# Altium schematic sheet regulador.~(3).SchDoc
size A4
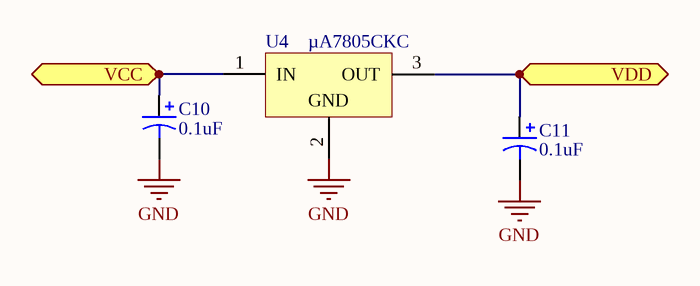
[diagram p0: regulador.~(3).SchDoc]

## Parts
C10  value 0.1uF  [CAPPR2.5-6.3X5]  (hidden comment: Cap Pol1 0.1u)
C11  value 0.1uF  [CAPPR2.5-6.3X5]  (hidden comment: Cap Pol1 0.1u)
U4  µA7805CKC  [To_220_H]

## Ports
VCC (in), VDD (out)

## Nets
GND: C10.2 C11.2 U4.2(GND)
VCC: C10.1 U4.1(IN) ; port VCC
VDD: C11.1 U4.3(OUT) ; port VDD

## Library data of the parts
C10 C11 = Cap Pol1: Polarized Capacitor (Radial)
U4 = µA7805CKC: Positive-Voltage Regulator; Note: Pin 2 is electrically connected to TAB.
